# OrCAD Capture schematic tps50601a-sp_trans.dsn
size B
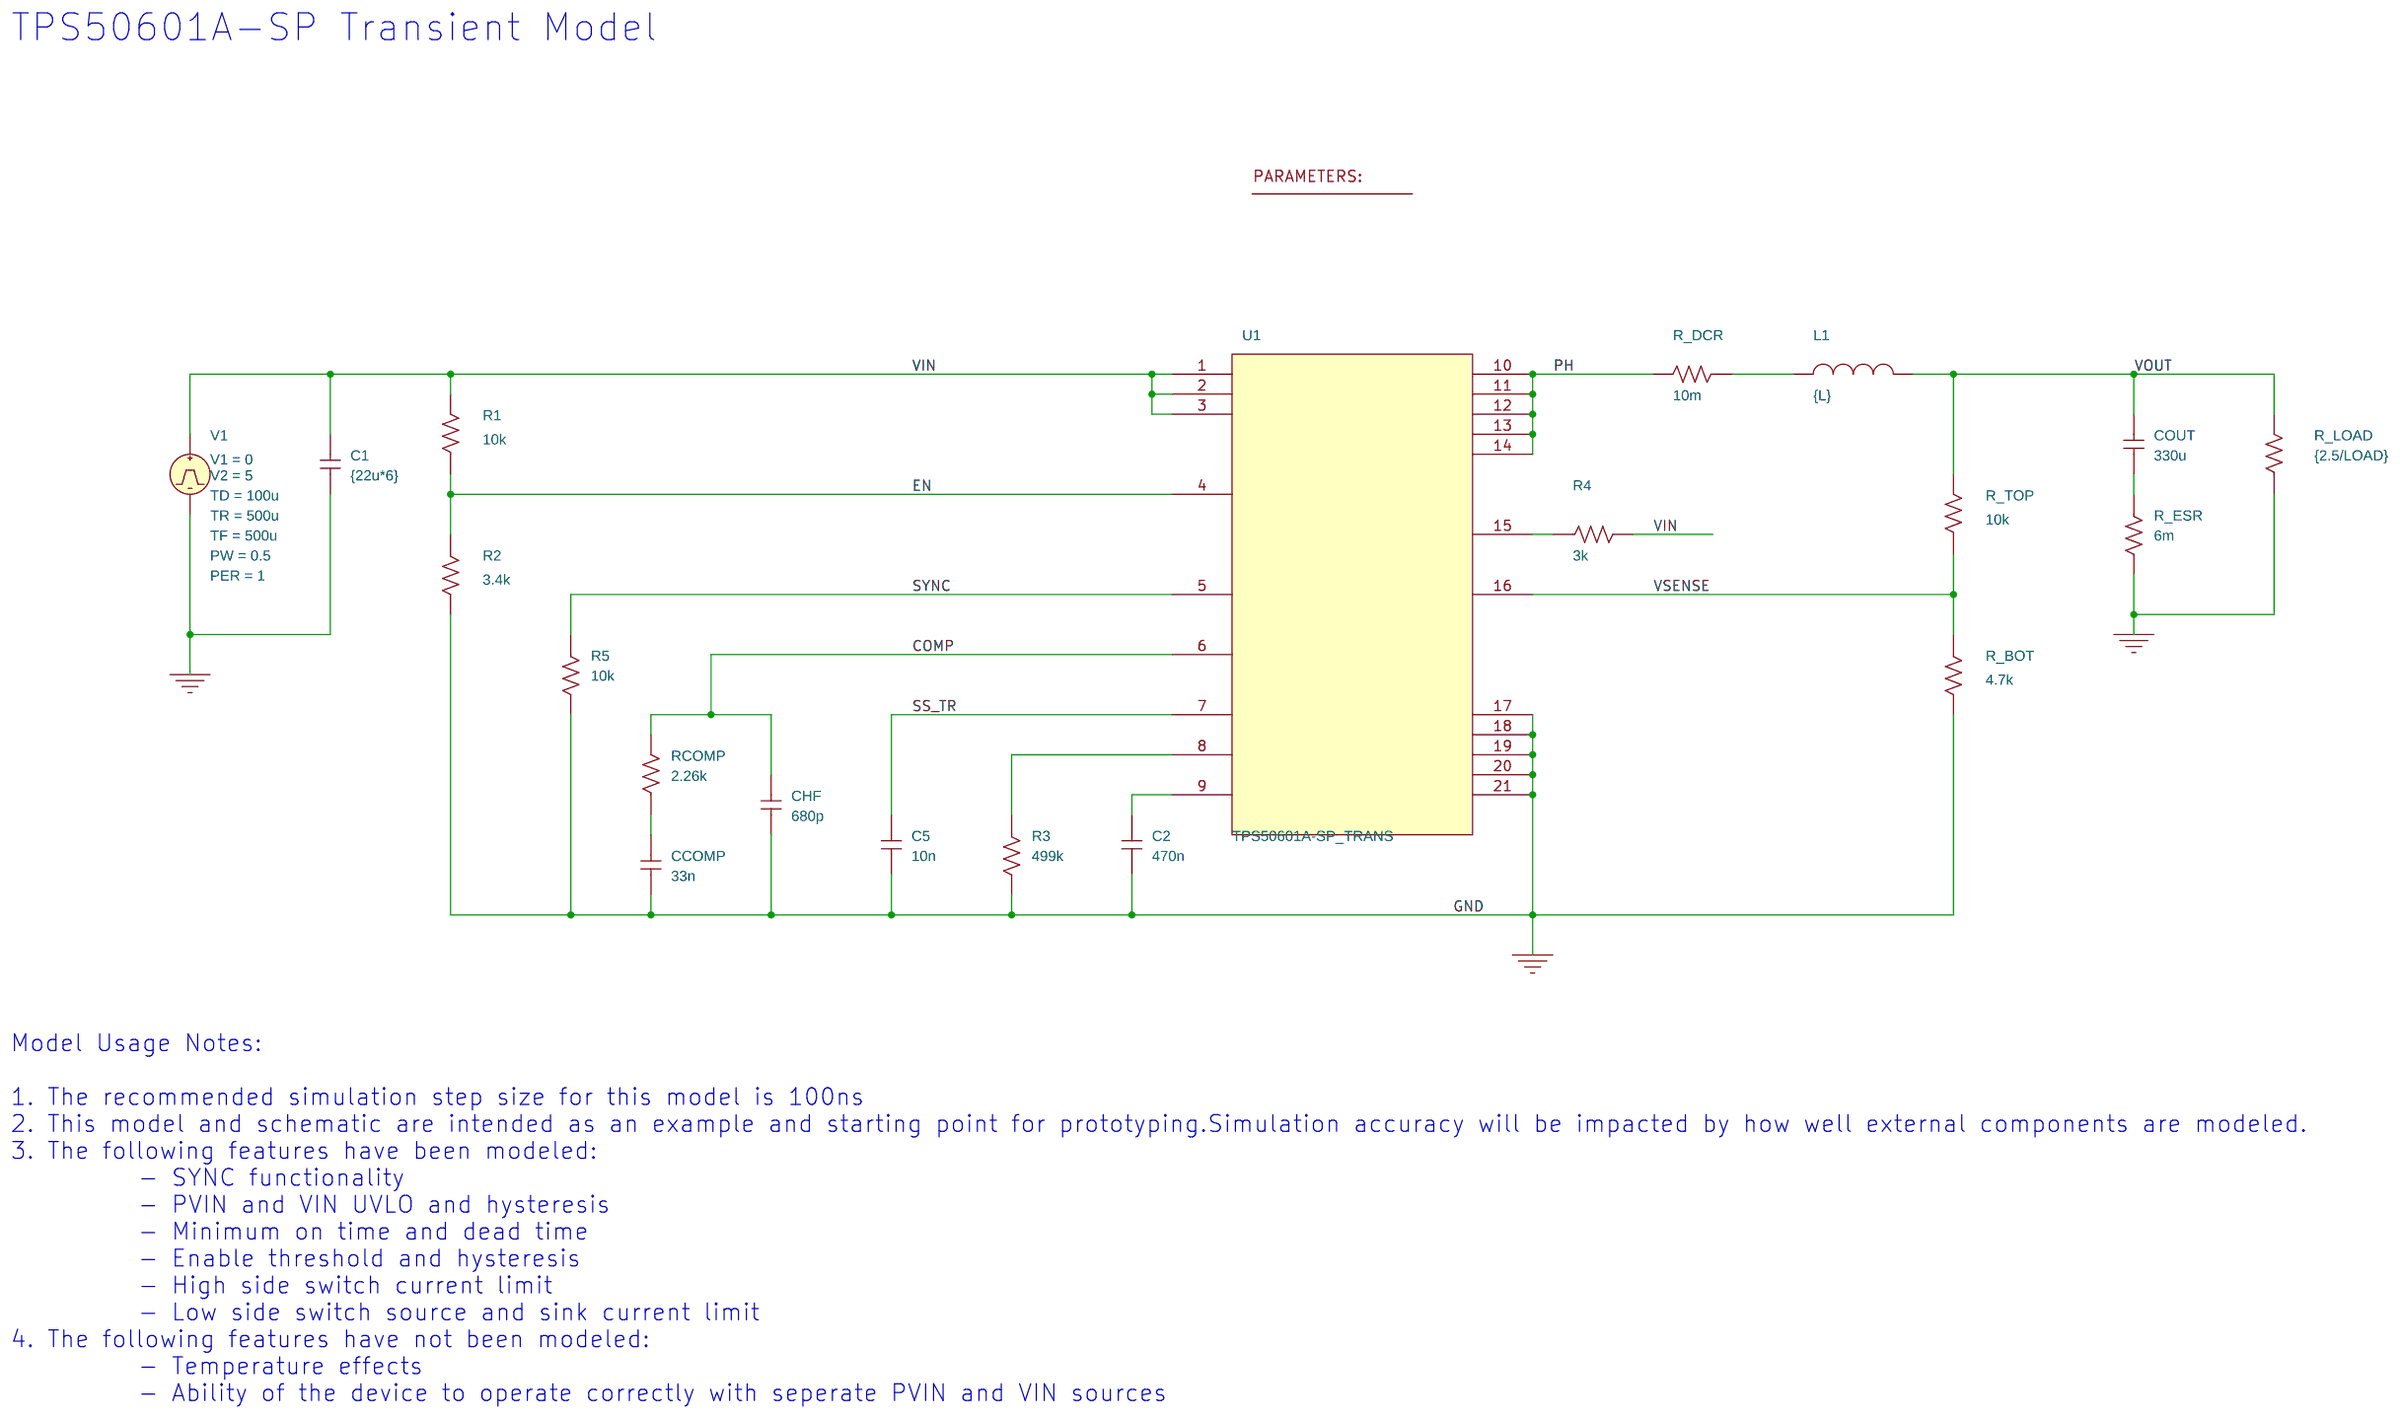
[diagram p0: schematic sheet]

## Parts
1  PARAM
C1  {22u*6}  [RAD/CK05]
C2  470n  [RAD/CK05]
C5  10n  [RAD/CK05]
CCOMP  33n  [RAD/CK05]
CHF  680p  [RAD/CK05]
COUT  330u  [RAD/CK05]
L1  {L}  [DISC/.350x.175/LS.200x.100/.034]
R1  10k  [AX/RC05]
R2  3.4k  [AX/RC05]
R3  499k  [AX/RC05]
R4  3k  [AX/RC05]
R5  10k  [AX/RC05]
R_BOT  4.7k  [AX/RC05]
R_DCR  10m  [AX/RC05]
R_ESR  6m  [AX/RC05]
R_LOAD  {2.5/LOAD}  [AX/RC05]
R_TOP  10k  [AX/RC05]
RCOMP  2.26k  [AX/RC05]
U1  TPS50601A-SP_TRANS
V1  VPULSE

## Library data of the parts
1 = PARAM: L: 4.7u; LOAD: 6
C1 C2 C5 CCOMP CHF COUT = C
L1 = L
R1-R5 R_BOT R_DCR R_ESR R_LOAD R_TOP RCOMP = R
U1 = TPS50601A-SP_TRANS_17
V1 = VPULSE: PER: 1; PW: 0.5; TD: 100u; TF: 500u; TR: 500u; V1: 0; V2: 5

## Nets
VIN: C1.1 R1.2 R4.2 U1.1(VIN) U1.2(PVIN_0) U1.3(PVIN_1) V1.1(+)
0: C1.2 C2.2 C5.2 CCOMP.2 CHF.2 R2.2 R3.2 R5.2 R_BOT.2 R_ESR.2 R_LOAD.1 U1.17(AGND) U1.18(PGND_0) U1.19(PGND_1) U1.20(PGND_2) U1.21(PWPD) V1.2(-)
COMP: CHF.1 RCOMP.2 U1.6(COMP)
EN: R1.1 R2.1 U1.4(EN)
PH: R_DCR.2 U1.10(PH_0) U1.11(PH_1) U1.12(PH_2) U1.13(PH_3) U1.14(PH_4)
SS_TR: C5.1 U1.7(SS_TR)
SYNC: R5.1 U1.5(SYNC)
VOUT: COUT.1 L1.2 R_LOAD.2 R_TOP.2
VSENSE: R_BOT.1 R_TOP.1 U1.16(VSENSE)
N16769091: L1.1 R_DCR.1
N16769243: COUT.2 R_ESR.1
N16769525: CCOMP.1 RCOMP.1
N16782627: C2.1 U1.9(REFCAP)
N16786696: R3.1 U1.8(RT)
N16792841: R4.1 U1.15(PWRGD)

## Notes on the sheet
- TPS50601A-SP Transient Model
- Model Usage Notes:
  1. The recommended simulation step size for this model is 100ns
  2. This model and schematic are intended as an example and starting point for prototyping.Simulation accuracy will be impacted by how well external components are modeled.
  3. The following features have been modeled:
            - SYNC functionality
            - PVIN and VIN UVLO and hysteresis
            - Minimum on time and dead time
            - Enable threshold and hysteresis
            - High side switch current limit
            - Low side switch source and sink current limit
  4. The following features have not been modeled:
            - Temperature effects
            - Ability of the device to operate correctly with seperate PVIN and VIN sources
